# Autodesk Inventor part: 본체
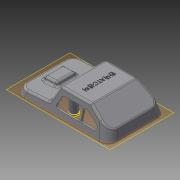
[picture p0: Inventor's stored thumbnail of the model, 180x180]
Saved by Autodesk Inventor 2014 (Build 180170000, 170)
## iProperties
Created: 2015-05
Part Number: 본체
Material: Generic
Document SubType Name: Modeling
Designer: Administrator
Density: 1 g/cm^3
Appearance: Default
Author: Administrator
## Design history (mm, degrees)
sketch "스케치4"
  geometry: L1 (61, 0)-(-61, 0); L2 (-61, 0)-(-57.738, 12.175); L3 (-57.738, 12.175)-(-31, 30); L4 (-31, 30)-(9.684, 30); L5 (19, 10.201)-(58.826, 8.114); L6 (58.826, 8.114)-(61, 0); L7 (-57.738, 12.175)-(-61, 10); L8 (-61, 0)-(-61, 10); L9 (61, 0)-(61, 8); L10 (58.826, 8.114)-(61, 8); L11 (19, 10.201)-(9.684, 30); 2 further points
  constraints: 22 end point, 2 collinear, 2 parallel, 1 coincident, 1 horizontal, 1 midpoint, 1 perpendicular
  dimensions: "d35" = 122 distance of L1.start L1.end; "d36" = 8 distance of L1.start L9.end; "d37" = 3 deg angle of L1 L5; "d38" = 105 deg angle of L1 L6; "d39" = 30 distance between parallel lines of L1 L4; "d40" = 20 vertical distance of L7.end L3.end; "d41" = 30 horizontal distance of L3.end L7.end; "d42" = 105 deg angle of L1 L2; "d46" = 42 horizontal distance of L5.start L1.start
extrude "돌출1" new body sketch "스케치4" stored distance "d44" = 76; taper "d45" = 0 deg
sketch "스케치5"
  geometry: L1 (19, 10.201)-(58.826, 8.114) reference; L2 (50.015, 8.576)-(48.459, 13.664); L3 (48.459, 13.664)-(32.122, 14.52); L4 (32.122, 14.52)-(30.042, 9.622); L5 (58.826, 8.114)-(61, 8); L6 (61, 0)-(58.826, 8.114) reference; L7 (61, 0)-(61, 8); 1 further point
  constraints: 10 end point, 2 parallel, 2 point on line, 1 vertical
  dimensions: "d47" = 11 distance of L5.end L2.start; "d48" = 20 distance of L2.start L4.end; "d49" = 5 distance between parallel lines of L1 L3; "d50" = 70 deg angle of L1 L4; "d51" = 70 deg angle of L1 L2
extrude "돌출2" join sketch "스케치5" stored distance "d52" = 26; taper "d53" = 0 deg
fillet "모깎기1" dims "d54" = 3
fillet "모깎기2" dims "d55" = 3
node "작업 평면1"
sketch "스케치6"
  geometry: L1 (0, 0)-(-76, 0) reference; L2 (0, 0)-(-8.038, 30); L3 (-76, 0)-(-67.962, 30); L4 (-76, 10.201)-(-76, 30) reference; L5 (-76, 30)-(0, 30) reference; L6 (0, 30)-(0, 10.201) reference; L7 (-67.962, 30)-(-76, 30); L8 (-8.038, 30)-(0, 30); L9 (0, 0)-(0, 30); L10 (-76, 0)-(-76, 30); 1 further point
  constraints: 12 end point, 4 collinear, 2 point on line
  dimensions: "d56" = 105 deg angle of L1 L3; "d57" = 105 deg angle of L1 L2
extrude "돌출3" cut sketch "스케치6" stored distance "d58" = 26; taper "d59" = 0 deg
fillet "모깎기3" dims "d60" = 12
fillet "모깎기4" dims "d61" = 3
node "작업 평면2"
sketch "스케치7"
  geometry: A1 r 4 centre (5.409, 0) between (9.409, 0) and (1.409, 0); A2 r 4 centre (16.409, 0) between (20.409, 0) and (12.409, 0); A3 r 4 centre (36.409, 0) between (40.409, 0) and (32.409, 0); A4 r 4 centre (47.409, 0) between (51.409, 0) and (43.409, 0); 9 further points
  constraints: 8 point on circle, 5 horizontal alignment, 4 centre point, 15 other
  dimensions: "d62" = 8 diameter of A1; "d63" = 8 diameter of A2; "d64" = 8 diameter of A3; "d66" = 10 distance of A2.centre point (26.409, 0); "d67" = 11 distance of A1.centre A2.centre; "d68" = 10 distance of point (26.409, 0) A3.centre; "d69" = 11 distance of A3.centre A4.centre; "d70" = 8 diameter of A4
extrude "돌출4" join sketch "스케치7" stored distance "d71" = 26; taper "d72" = 0 deg
sketch "스케치8"
  geometry: L1 (0, -9.409)-(0, -1.409) reference; L2 (0, -20.409)-(0, -12.409) reference; L3 (0, -40.409)-(0, -32.409) reference; L4 (0, -51.409)-(0, -43.409) reference; L5 (0, -51.409)-(0, -43.409) reference; A1 r 4 centre (0, -5.409) between (0, -9.409) and (0, -1.409) reference; A2 r 4 centre (0, -16.409) between (0, -20.409) and (0, -12.409) reference; A3 r 4 centre (0, -36.409) between (0, -40.409) and (0, -32.409) reference; A4 r 4 centre (0, -47.409) between (0, -51.409) and (0, -43.409) reference; 1 further point
extrude "돌출5" join sketch "스케치8" distance "d73" = 2; taper "d74" = 0 deg
chamfer "모따기1" distance "d75" = 1; stored, may be unused: second distance "d76" = 2, angle "d77" = 45 deg
feature "쉘1" dims "d78" = 2
sketch "스케치9"
  geometry: L1 (68.78, -1.251)-(68.78, -54.068) reference; 2 further points
  constraints: 1 horizontal alignment, 1 other
  dimensions: "d79" = 50 distance from line of L1 point (18.78, -27.66)
feature "엠보싱1" sketch "스케치9" dims "d48" = 20, "d80" = 0.5, "d81" = 0
node "작업 평면3"
sketch "스케치11"
  geometry: L1 (-15.521, 11.325)-(-7.78, 27.776) reference; L2 (-7.78, 27.776)-(30.092, 27.776) reference; L3 (30.092, 27.776)-(44.549, 18.138) reference; L4 (44.549, 18.138)-(49.409, 0) reference; L5 (-5.418, 21.054)-(-9.652, 12.054); L6 (-6.938, 7.776)-(19.335, 7.776); L7 (22.335, 10.776)-(22.335, 19.776); L8 (19.335, 22.776)-(-2.703, 22.776); L9 (26.078, 22.776)-(27.669, 22.776); L10 (29.334, 22.273)-(42.834, 13.273); L11 (41.169, 7.776)-(26.078, 7.776); L12 (23.078, 10.776)-(23.078, 19.776); A1 r 6 centre (-20.95, 13.88) between (-20.636, 7.888) and (-15.521, 11.325) reference; A2 r 3 centre (-6.938, 10.776) between (-9.652, 12.054) and (-6.938, 7.776); A3 r 3 centre (-2.703, 19.776) between (-2.703, 22.776) and (-5.418, 21.054); A4 r 3 centre (19.335, 19.776) between (22.335, 19.776) and (19.335, 22.776); A5 r 3 centre (19.335, 10.776) between (19.335, 7.776) and (22.335, 10.776); A6 r 3 centre (26.078, 10.776) between (23.078, 10.776) and (26.078, 7.776); A7 r 3 centre (26.078, 19.776) between (26.078, 22.776) and (23.078, 19.776); A8 r 3 centre (27.669, 19.776) between (29.334, 22.273) and (27.669, 22.776); A9 r 3 centre (41.169, 10.776) between (41.169, 7.776) and (42.834, 13.273); 3 further points
  constraints: 16 end point, 16 point on circle, 16 tangent, 8 centre point, 7 equal radius, 4 parallel, 4 point on line, 3 perpendicular, 1 collinear
  dimensions: "d83" = 5 distance between parallel lines of L2 L8; "d84" = 5 distance between parallel lines of L2 L9; "d85" = 5 distance between parallel lines of L10 L3; "d86" = 5 distance between parallel lines of L1 L5; "d87" = 34 distance from line of point (-11.665, 7.776) L7; "d88" = 15 distance between parallel lines of L11 L9; "d89" = 15 distance between parallel lines of L6 L8; "d90" = 28 distance from line of L12 point (51.078, 7.776); "d91" = 3 radius of A2
extrude "돌출6" cut sketch "스케치11" stored distance "d92" = 10; taper "d93" = 0 deg
sketch "스케치12"
  geometry: L1 (98.679, -73.929)-(0.139, -73.929) reference; L2 (-9.521, -64.27)-(-9.521, -11.73) reference; L3 (0.139, -2.071)-(98.679, -2.071) reference; L4 (108.338, -11.73)-(108.338, -15) reference; L5 (108.338, -15)-(110.409, -15) reference; L6 (110.409, -15)-(110.409, -19) reference; L7 (110.409, -19)-(108.338, -19) reference; L8 (108.338, -19)-(108.338, -26) reference; L9 (108.338, -26)-(110.409, -26) reference; L10 (110.409, -26)-(110.409, -30) reference; L11 (110.409, -30)-(108.338, -30) reference; L12 (108.338, -30)-(108.338, -46) reference; L13 (108.338, -46)-(110.409, -46) reference; L14 (110.409, -46)-(110.409, -50) reference; L15 (110.409, -50)-(108.338, -50) reference; L16 (108.338, -50)-(108.338, -57) reference; L17 (108.338, -57)-(110.409, -57) reference; L18 (110.409, -57)-(110.409, -61) reference; L19 (110.409, -61)-(108.338, -61) reference; L20 (108.338, -61)-(108.338, -64.27) reference; L21 (0, 0)-(98.818, 0) reference; L22 (98.679, -1)-(0.139, -1); L23 (-10.591, -11.73)-(-10.591, -64.27); L24 (0.139, -75)-(98.679, -75); L25 (109.409, -64.27)-(109.409, -62.071); L26 (109.409, -62.071)-(111.479, -62.071); L27 (111.479, -62.071)-(111.479, -55.929); L28 (111.479, -55.929)-(109.409, -55.929); L29 (109.409, -55.929)-(109.409, -51.071); L30 (109.409, -51.071)-(111.479, -51.071); L31 (111.479, -51.071)-(111.479, -44.929); L32 (111.479, -44.929)-(109.409, -44.929); L33 (109.409, -44.929)-(109.409, -31.071); L34 (109.409, -31.071)-(111.479, -31.071); L35 (111.479, -31.071)-(111.479, -24.929); L36 (111.479, -24.929)-(109.409, -24.929); L37 (109.409, -24.929)-(109.409, -20.071); L38 (109.409, -20.071)-(111.479, -20.071); L39 (111.479, -20.071)-(111.479, -13.929); L40 (111.479, -13.929)-(109.409, -13.929); L41 (109.409, -13.929)-(109.409, -11.73); 5 further points; 4 other entities
  constraints: 40 end point, 7 parallel, 32 other
  dimensions: "d94" = 1 distance between parallel lines of L21 L22
extrude "돌출7" join sketch "스케치12" distance "d95" = 1; taper "d96" = 0 deg
sketch "스케치14"
  geometry: C1 r 5 at (-40, 0); C2 r 5 at (0, -22); C3 r 5 at (0, 22); C4 r 5 at (40, 0); 1 further point
  constraints: 4 centre point, 2 horizontal alignment, 2 vertical alignment
  dimensions: "d97" = 10 diameter of C1; "d98" = 10 diameter of C2; "d99" = 10 diameter of C3; "d100" = 10 diameter of C4; "d101" = 40 horizontal distance of C3.centre C1.centre; "d102" = 40 distance of point (0, 0) C4.centre; "d103" = 22 distance of point (0, 0) C3.centre; "d104" = 22 distance of point (0, 0) C2.centre
extrude "돌출8" join sketch "스케치14" stored distance "d105" = 1; taper "d106" = 0 deg
node "작업 평면4"
sketch "스케치16"
  geometry: L1 (-5, 0)-(5, 0) reference; L2 (5, 28)-(-5, 28) reference; L3 (5, 0)-(5, 28) reference; L4 (-5, 0)-(-5, 28) reference; 1 further point
  node "투영된 루프4"
sketch "스케치17"
  geometry: C1 r 5 at (0, 0) reference; C2 r 5 at (-40, 22) reference; C3 r 5 at (0, 44) reference; C4 r 5 at (40, 22) reference; 1 further point
  node "투영된 루프5"
  node "투영된 루프6"
  node "투영된 루프7"
node "작업 평면5"
sketch "스케치18"
  geometry: C1 r 5 at (0, -22) reference; C2 r 5 at (0, 22) reference; C3 r 5 at (40, 0) reference; C4 r 5 at (-40, 0) reference; 4 further points
  constraints: 4 coincident
  node "투영된 루프8"
  node "투영된 루프9"
  node "투영된 루프10"
  node "투영된 루프11"
node "솔리드1"
node "투영된 루프1"
node "투영된 루프2"
node "투영된 루프3"
other parameters: "d82" = -38, "d107" = -22, "d108" = 2
